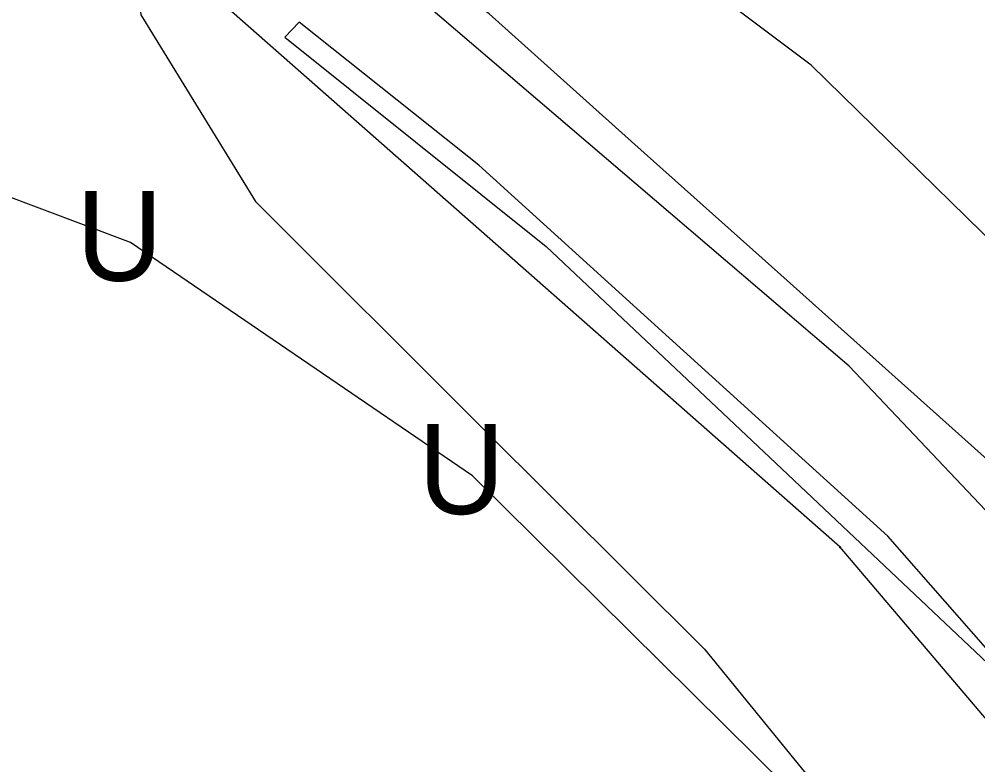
# Model space of a CAD drawing. Extents: x 1050807 to 1053552, y 395828 to 398415.
# Drawn here: x 1051909.5 to 1051973.5, y 397939 to 397988.8 of the extents above; entities that cross this region are included whole.
import ezdxf

# ---------------------------------------------------------------- set-up
doc = ezdxf.new("R2010")
doc.units = 0
for name, color, linetype in [('Default', 7, 'Continuous'), ('S_DITCHLINE', 7, 'Continuous'), ('S_EDGE_PAVEMENT', 7, 'Continuous'), ('S_GRAVEL_ROAD', 7, 'Continuous'), ('S_PAVEMENT_CROWN', 7, 'Continuous'), ('S_SHOULDER', 7, 'Continuous'), ('S_UNDERGROUND_CABLE', 7, 'Continuous'), ('S_UTL_PT_SYM', 7, 'Continuous'), ('S_WATER_UTILITIES', 7, 'Continuous')]:
    doc.layers.add(name, color=color, linetype=linetype)

msp = doc.modelspace()

# ---------------------------------------------------------------- linework, layer by layer
at = {"layer": 'S_DITCHLINE'}
msp.add_lwpolyline([(1052044.565, 397837.018), (1052042.709, 397843.024), (1052034.556, 397860.054), (1052026.404, 397877.085), (1052014.154, 397896.072), (1052001.905, 397915.06), (1051993.297, 397924.871), (1051984.69, 397934.682), (1051976.083, 397944.493), (1051967.475, 397954.304), (1051953.82, 397966.686), (1051940.165, 397979.068), (1051928.173, 397988.617), (1051927.227, 397987.623), (1051944.651, 397973.64), (1051959.581, 397959.551), (1051974.511, 397945.462), (1051988.397, 397928.836), (1052002.283, 397912.209), (1052012.588, 397896.277), (1052022.894, 397880.344), (1052031.803, 397862.087), (1052040.713, 397843.83), (1052043.637, 397836.55)], dxfattribs=at)
at = {"layer": 'S_EDGE_PAVEMENT'}
msp.add_lwpolyline([(1052038.693, 397873.189), (1052032.041, 397883.851), (1052025.39, 397894.512), (1052018.738, 397905.173), (1052012.087, 397915.835), (1052004.017, 397925.455), (1051995.948, 397935.075), (1051987.879, 397944.696), (1051979.809, 397954.316), (1051970.068, 397963.029), (1051960.327, 397971.742), (1051950.586, 397980.455), (1051940.845, 397989.169), (1051920.673, 398003.534), (1051900.024, 398015.697), (1051879.375, 398027.861), (1051867.402, 398032.674), (1051855.428, 398037.486), (1051843.455, 398042.299), (1051831.481, 398047.112), (1051807.632, 398052.862)], dxfattribs=at)
at = {"layer": 'S_GRAVEL_ROAD'}
msp.add_lwpolyline([(1051907.199, 398003.548), (1051915.884, 398002.907), (1051917.599, 397989.103), (1051925.255, 397976.639), (1051940.238, 397961.7), (1051955.221, 397946.762), (1051966.382, 397933.093), (1051977.542, 397919.423), (1051982.832, 397903.764), (1051988.123, 397888.106), (1051995.105, 397874.287), (1052002.088, 397860.468), (1052012.077, 397846.725), (1052024.659, 397838.002)], dxfattribs=at)
at = {"layer": 'S_PAVEMENT_CROWN'}
msp.add_lwpolyline([(1052041.362, 397889.369), (1052035.084, 397900.285), (1052028.805, 397911.201), (1052020.993, 397921.227), (1052013.181, 397931.253), (1052005.369, 397941.279), (1051997.558, 397951.305), (1051979.948, 397968.52), (1051962.338, 397985.735), (1051944.748, 397998.964), (1051927.159, 398012.192), (1051916.296, 398018.661), (1051905.432, 398025.13), (1051894.569, 398031.599), (1051883.705, 398038.068), (1051871.837, 398042.851), (1051859.968, 398047.634), (1051848.099, 398052.416), (1051836.231, 398057.199), (1051823.738, 398060.254), (1051811.245, 398063.309)], dxfattribs=at)
at = {"layer": 'S_SHOULDER'}
msp.add_lwpolyline([(1052050.553, 397842.577), (1052039.7, 397864.607), (1052028.848, 397886.638), (1052021.355, 397897.418), (1052013.861, 397908.198), (1052006.368, 397918.978), (1051998.875, 397929.758), (1051981.877, 397947.71), (1051964.879, 397965.662), (1051950.671, 397977.794), (1051936.464, 397989.927), (1051922.291, 398000.291)], dxfattribs=at)
at = {"layer": 'S_UNDERGROUND_CABLE'}
for p, q in [((1051916.911, 397973.901), (1051890.757, 397983.754)), ((1051939.744, 397958.334), (1051916.911, 397973.901)), ((1051984.34, 397914.246), (1051939.744, 397958.334))]:
    msp.add_line(p, q, dxfattribs=at)
at = {"layer": 'S_UTL_PT_SYM'}
msp.add_lwpolyline([(1051964.276, 397953.57), (1051964.276, 397953.62), (1051964.276, 397953.57), (1051964.226, 397953.57), (1051964.276, 397953.57), (1051964.276, 397953.52), (1051964.276, 397953.57), (1051964.326, 397953.57)], dxfattribs=at)
at = {"layer": 'S_WATER_UTILITIES'}
for p, q in [((1051964.276, 397953.57), (1051923.282, 397989.653)), ((1051999.408, 397912.237), (1051964.276, 397953.57))]:
    msp.add_line(p, q, dxfattribs=at)

# ---------------------------------------------------------------- texts
at = {"layer": 'Default'}
for p in [(1051913.282, 397971.356), (1051936.115, 397955.789)]:
    msp.add_text('U', height=6, dxfattribs=at).set_placement(p)

doc.saveas('drawing.dxf')
